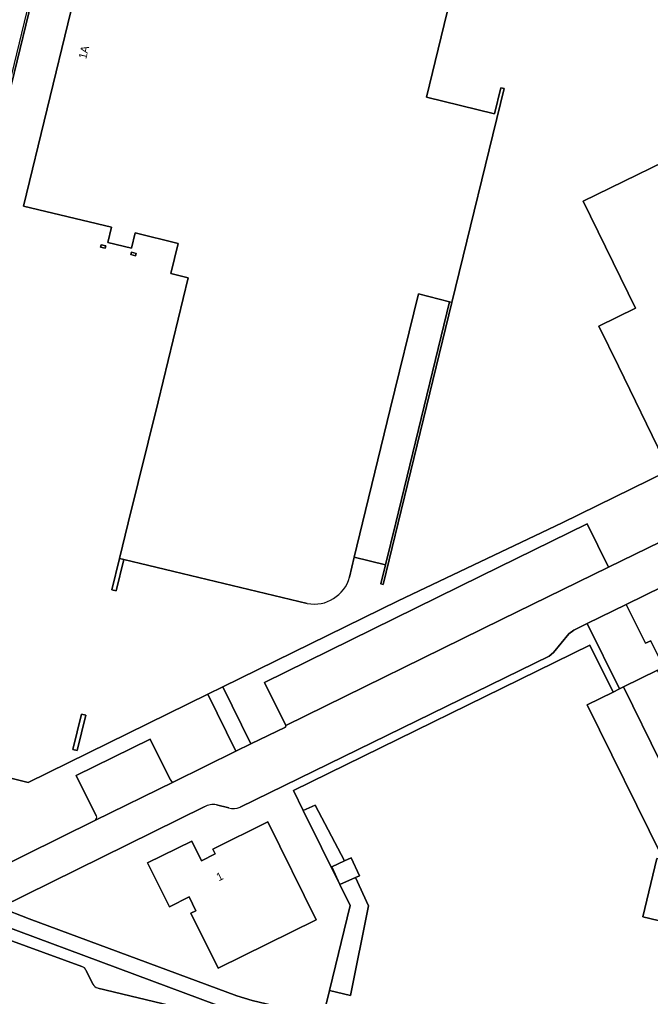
# Model space of a CAD drawing. Extents: x 163043 to 165076, y 382019 to 382874.
# Drawn here: x 163174.8 to 163253.6, y 382690.8 to 382812.9 of the extents above; entities that cross this region are included whole.
import ezdxf

# ---------------------------------------------------------------- set-up
doc = ezdxf.new("R2010")
doc.units = 0
for name, color, linetype in [('IMGEO_Erf', 7, 'Continuous'), ('IMGEO_Fietspad_open', 7, 'Continuous'), ('IMGEO_Groenvoorziening', 7, 'Continuous'), ('IMGEO_Hek', 7, 'Continuous'), ('IMGEO_Loofbos', 7, 'Continuous'), ('IMGEO_Muur', 7, 'Continuous'), ('IMGEO_Pand', 7, 'Continuous'), ('IMGEO_Pand_nummerreeks', 7, 'Continuous'), ('IMGEO_Parkeervlak_open', 7, 'Continuous'), ('IMGEO_Rijbaan_lokaal_gesloten', 7, 'Continuous'), ('IMGEO_Rijbaan_lokaal_open', 7, 'Continuous'), ('IMGEO_Voetpad_open', 7, 'Continuous')]:
    doc.layers.add(name, color=color, linetype=linetype)

msp = doc.modelspace()

# ---------------------------------------------------------------- linework, layer by layer
at = {"layer": 'IMGEO_Erf'}
for points in [[(163360.61, 382802.83), (163320.19, 382810.11), (163314.65, 382811.1), (163314.26, 382811.17), (163314.35, 382812.18), (163260.67, 382823.11), (163260.43, 382821.93), (163260.28, 382821.96), (163252.7, 382823.52), (163242.43, 382825.65), (163242.33, 382825.25), (163240, 382825.68), (163241.32, 382832.3), (163232.1, 382834.21), (163234.48, 382827.11), (163183.14, 382837.73), (163182.27, 382837.91), (163182.21, 382837.62), (163181.79, 382837.7), (163171.55, 382795.71), (163170.41, 382791.08), (163170.29, 382791.11)], [(163229.29, 382818.25), (163225.61, 382803.16), (163234.14, 382801.08), (163234.93, 382804.33), (163235.33, 382804.24), (163228.81, 382777.5), (163222.11, 382750), (163220.23, 382742.28)], [(163210.74, 382739.91), (163187.82, 382745.42), (163186.87, 382741.49), (163186.35, 382741.62), (163187.29, 382745.55), (163188.39, 382750), (163192.11, 382765.11), (163195.86, 382780.59), (163193.71, 382781.12), (163194.64, 382784.88), (163189.27, 382786.19), (163188.81, 382784.29), (163185.83, 382785), (163186.29, 382786.91), (163175.29, 382789.56), (163181.21, 382813.84)], [(163170.08, 382790.67), (163166.83, 382776.84), (163169.38, 382776.24), (163169.07, 382774.97), (163168.15, 382770.94), (163167.89, 382771), (163167.47, 382769.28), (163156.04, 382722.53), (163161.49, 382721.16), (163163.24, 382720.72), (163175.88, 382717.55), (163198.33, 382728.59), (163200.21, 382729.51), (163222.08, 382740.26), (163242.58, 382750), (163320.84, 382788.38)], [(163220.23, 382742.28), (163219.93, 382742.36), (163220.5, 382744.72), (163216.6, 382745.71), (163216.01, 382743.2)]]:
    msp.add_lwpolyline(points, dxfattribs=at)
for points in [[(163260.37, 382797.58), (163257.72, 382803.04), (163272.56, 382810.28), (163275.22, 382804.81), (163285.92, 382810.05), (163288.8, 382804.14), (163299.84, 382781.52), (163300.53, 382780.1), (163259.8, 382760.22), (163255.22, 382757.98), (163249.59, 382769.57), (163247.16, 382774.53), (163251.73, 382776.78), (163245.19, 382790.17)], [(163185.58, 382784.57), (163185.5, 382784.28), (163184.92, 382784.43), (163185, 382784.72)], [(163189.29, 382783.33), (163188.71, 382783.49), (163188.79, 382783.78), (163189.37, 382783.62)], [(163182.01, 382721.54), (163181.48, 382721.67), (163182.56, 382726.09), (163183.08, 382725.96)]]:
    msp.add_lwpolyline(points, close=True, dxfattribs=at)
msp.add_arc((163211.6, 382744.41), 4.58, 259.2784, 344.701, dxfattribs=at)
at = {"layer": 'IMGEO_Fietspad_open'}
msp.add_lwpolyline([(163172.54, 382699.75), (163201.62, 382688.96), (163202.36, 382688.7), (163203.95, 382688.31), (163252.01, 382676.83), (163252.46, 382678.73), (163203.88, 382690.32), (163201.96, 382690.91), (163176, 382700.52), (163172.35, 382701.93), (163168.8, 382700.21), (163171.68, 382699.94)], close=True, dxfattribs=at)
at = {"layer": 'IMGEO_Groenvoorziening'}
for points in [[(163181.79, 382837.7), (163182.21, 382837.62), (163182.27, 382837.91), (163183.69, 382844.16), (163173.42, 382846.23), (163165.78, 382803.62), (163171.55, 382795.71)], [(163253.66, 382735.24), (163252.99, 382734.96), (163250.57, 382739.8), (163245.68, 382737.41), (163249.72, 382729.24), (163250.24, 382729.49), (163254.47, 382731.57), (163266.57, 382707.08), (163265.7, 382703.66), (163271.64, 382702.24), (163272.62, 382706.27), (163267.35, 382707.42)]]:
    msp.add_lwpolyline(points, close=True, dxfattribs=at)
for points in [[(163320.84, 382788.38), (163242.58, 382750), (163222.08, 382740.26), (163200.21, 382729.51), (163203.71, 382722.37), (163208.02, 382724.48), (163208.06, 382724.68), (163205.42, 382730.04), (163232.39, 382743.33), (163245.68, 382749.88), (163248.36, 382744.45), (163259.7, 382750)], [(163271.32, 382750), (163250.57, 382739.8), (163252.99, 382734.96), (163253.66, 382735.24)], [(163194.09, 382717.65), (163201.83, 382721.45), (163198.33, 382728.59), (163175.88, 382717.55), (163163.24, 382720.72), (163159.5, 382704.97), (163166.78, 382704.19), (163184.23, 382712.81)], [(163181.88, 382718.44), (163191.13, 382722.98), (163193.64, 382717.92)], [(163184.4, 382713.38), (163181.88, 382718.44)]]:
    msp.add_lwpolyline(points, dxfattribs=at)
for centre, radius, start, end in [((163194, 382718.02), 0.379, 195.2459, 283.2376), ((163184.01, 382713.19), 0.438, 299.8007, 25.7543)]:
    msp.add_arc(centre, radius, start, end, dxfattribs=at)
at = {"layer": 'IMGEO_Hek'}
for points in [[(163182.27, 382837.91), (163181.98, 382837.97), (163181.57, 382838.06), (163171.31, 382795.84), (163168.94, 382796.43)], [(163359.37, 382797.83), (163352.45, 382797.4), (163349.43, 382797.09), (163343.5, 382795.94), (163337.67, 382794.6), (163334.82, 382793.72), (163329.21, 382791.76), (163326.4, 382790.68), (163320.84, 382788.38), (163242.58, 382750), (163222.08, 382740.26)], [(163222.08, 382740.26), (163175.88, 382717.55), (163161.49, 382721.16)]]:
    msp.add_lwpolyline(points, dxfattribs=at)
at = {"layer": 'IMGEO_Loofbos'}
msp.add_lwpolyline([(163245.69, 382727.26), (163248.93, 382728.85), (163246.01, 382734.71), (163209.01, 382716.54), (163210.24, 382714.06), (163211.73, 382714.73), (163215.4, 382707.75), (163216.23, 382708.13), (163217.25, 382705.9), (163216.76, 382705.68), (163218.39, 382702.14), (163216.15, 382690.95), (163213.5, 382691.55), (163213.05, 382689.7), (163252.81, 382680.18), (163257.5, 382699.61), (163252.63, 382700.77), (163254.38, 382708.07), (163259.27, 382706.86), (163259.68, 382708.74), (163259.48, 382710.67), (163254.98, 382708.45)], close=True, dxfattribs=at)
at = {"layer": 'IMGEO_Muur'}
for points in [[(163220.5, 382744.72), (163219.93, 382742.36), (163220.23, 382742.28), (163222.11, 382750), (163228.81, 382777.5), (163228.51, 382777.59), (163221.79, 382750)], [(163186.87, 382741.49), (163187.82, 382745.42), (163187.29, 382745.55), (163186.35, 382741.62)], [(163182.56, 382726.09), (163181.48, 382721.67), (163182.01, 382721.54), (163183.08, 382725.96)]]:
    msp.add_lwpolyline(points, close=True, dxfattribs=at)
at = {"layer": 'IMGEO_Pand'}
for points in [[(163216.01, 382743.2), (163216.6, 382745.71), (163217.65, 382750), (163221.11, 382764.2), (163224.63, 382778.58), (163228.51, 382777.59), (163228.81, 382777.5), (163235.33, 382804.24), (163234.93, 382804.33), (163234.14, 382801.08), (163225.61, 382803.16), (163229.29, 382818.25)], [(163181.21, 382813.84), (163175.29, 382789.56), (163186.29, 382786.91), (163185.83, 382785), (163188.81, 382784.29), (163189.27, 382786.19), (163194.64, 382784.88), (163193.71, 382781.12), (163195.86, 382780.59), (163192.11, 382765.11), (163188.39, 382750), (163187.29, 382745.55), (163187.82, 382745.42), (163210.74, 382739.91)]]:
    msp.add_lwpolyline(points, dxfattribs=at)
for points in [[(163249.59, 382769.57), (163255.22, 382757.98), (163259.8, 382760.22), (163300.53, 382780.1), (163299.84, 382781.52), (163288.8, 382804.14), (163285.92, 382810.05), (163275.22, 382804.81), (163272.56, 382810.28), (163257.72, 382803.04), (163260.37, 382797.58), (163245.19, 382790.17), (163251.73, 382776.78), (163247.16, 382774.53)], [(163185.58, 382784.57), (163185, 382784.72), (163184.92, 382784.43), (163185.5, 382784.28)], [(163188.71, 382783.49), (163189.29, 382783.33), (163189.37, 382783.62), (163188.79, 382783.78)], [(163199.63, 382694.34), (163211.85, 382700.39), (163205.82, 382712.62), (163198.95, 382709.22), (163199.24, 382708.63), (163197.53, 382707.78), (163196.32, 382710.24), (163190.8, 382707.52), (163193.55, 382702.02), (163196.01, 382703.25), (163196.83, 382701.53), (163196.2, 382701.21)], [(163215.4, 382707.75), (163213.8, 382707.02), (163214.82, 382704.79), (163216.76, 382705.68), (163217.25, 382705.9), (163216.23, 382708.13)]]:
    msp.add_lwpolyline(points, close=True, dxfattribs=at)
msp.add_arc((163211.6, 382744.41), 4.58, 259.2784, 344.701, dxfattribs=at)
at = {"layer": 'IMGEO_Parkeervlak_open'}
for points in [[(163235.01, 382737.92), (163248.36, 382744.45), (163245.68, 382749.88), (163232.39, 382743.33), (163205.42, 382730.04), (163208.06, 382724.68)], [(163250.24, 382729.49), (163249.72, 382729.24), (163248.93, 382728.85), (163245.69, 382727.26), (163254.98, 382708.45), (163259.48, 382710.67)], [(163211.73, 382714.73), (163210.24, 382714.06), (163214.82, 382704.79), (163213.8, 382707.02), (163215.4, 382707.75)], [(163259.27, 382706.86), (163254.38, 382708.07), (163252.63, 382700.77), (163257.5, 382699.61)], [(163218.39, 382702.14), (163216.76, 382705.68), (163214.82, 382704.79), (163216.09, 382702.18), (163213.5, 382691.55), (163216.15, 382690.95)]]:
    msp.add_lwpolyline(points, close=True, dxfattribs=at)
for points in [[(163193.64, 382717.92), (163191.13, 382722.98), (163181.88, 382718.44), (163184.4, 382713.38)], [(163184.23, 382712.81), (163194.09, 382717.65)]]:
    msp.add_lwpolyline(points, dxfattribs=at)
for centre, radius, start, end in [((163194, 382718.02), 0.379, 195.2459, 283.2376), ((163184.01, 382713.19), 0.438, 299.8007, 25.7543)]:
    msp.add_arc(centre, radius, start, end, dxfattribs=at)
at = {"layer": 'IMGEO_Rijbaan_lokaal_gesloten'}
for points in [[(163323, 382780.97), (163259.7, 382750), (163248.36, 382744.45), (163235.01, 382737.92), (163208.06, 382724.68), (163208.02, 382724.48), (163203.71, 382722.37), (163201.83, 382721.45), (163194.09, 382717.65), (163184.23, 382712.81), (163166.78, 382704.19), (163164.05, 382702.84), (163162.09, 382701.87)], [(163202.36, 382714.48), (163240.95, 382733.35), (163241.47, 382733.79), (163243.4, 382736.12), (163244.02, 382736.59), (163245.68, 382737.41), (163250.57, 382739.8), (163271.32, 382750), (163327.66, 382777.68)], [(163157.18, 382701.57), (163165.67, 382698.64), (163168.07, 382699.85), (163168.61, 382700.12), (163168.8, 382700.21), (163172.35, 382701.93), (163197.88, 382714.53)], [(163199.4, 382714.75), (163200.93, 382714.39)], [(163182.59, 382694.58), (163168.65, 382699.64)], [(163183.98, 382692.36), (163183.15, 382694.06)], [(163251.29, 382675.9), (163203.7, 382687.3), (163184.58, 382691.88)]]:
    msp.add_lwpolyline(points, dxfattribs=at)
msp.add_lwpolyline([(163221.79, 382750), (163228.51, 382777.59), (163224.63, 382778.58), (163221.11, 382764.2), (163217.65, 382750), (163216.6, 382745.71), (163220.5, 382744.72)], close=True, dxfattribs=at)
for centre, radius, start, end in [((163198.95, 382712.61), 2.19, 77.9738, 119.014), ((163201.52, 382716.2), 1.91, 251.7554, 295.8303), ((163182.31, 382693.72), 0.902, 22.0668, 72.1754), ((163184.79, 382692.76), 0.899, 206.0966, 256.5137)]:
    msp.add_arc(centre, radius, start, end, dxfattribs=at)
at = {"layer": 'IMGEO_Rijbaan_lokaal_open'}
msp.add_lwpolyline([(163266.57, 382707.08), (163254.47, 382731.57), (163250.24, 382729.49), (163259.48, 382710.67), (163259.68, 382708.74), (163259.27, 382706.86), (163257.5, 382699.61), (163252.81, 382680.18), (163256.9, 382679.25), (163257.28, 382680.85), (163260.84, 382695.84), (163263.63, 382697.4), (163264.44, 382697.21), (163265.45, 382696.98), (163269.34, 382696.11), (163269.61, 382697.11), (163271.83, 382699.41), (163273.02, 382699.15), (163273.47, 382701.08), (163272.36, 382701.35), (163272.52, 382702.03), (163271.64, 382702.24), (163265.7, 382703.66)], close=True, dxfattribs=at)
at = {"layer": 'IMGEO_Voetpad_open'}
for points in [[(163216.09, 382702.18), (163214.82, 382704.79), (163210.24, 382714.06), (163209.01, 382716.54), (163246.01, 382734.71), (163248.93, 382728.85), (163249.72, 382729.24), (163245.68, 382737.41), (163244.02, 382736.59), (163243.4, 382736.12), (163241.47, 382733.79), (163240.95, 382733.35), (163202.36, 382714.48)], [(163197.88, 382714.53), (163172.35, 382701.93), (163176, 382700.52), (163201.96, 382690.91), (163203.88, 382690.32), (163252.46, 382678.73), (163252.81, 382680.18), (163213.05, 382689.7), (163213.5, 382691.55), (163216.09, 382702.18)], [(163200.93, 382714.39), (163199.4, 382714.75)], [(163168.65, 382699.64), (163182.59, 382694.58)], [(163251.88, 382676.26), (163252.01, 382676.83), (163203.95, 382688.31), (163202.36, 382688.7), (163201.62, 382688.96), (163172.54, 382699.75)], [(163183.15, 382694.06), (163183.98, 382692.36)], [(163184.58, 382691.88), (163203.7, 382687.3), (163251.29, 382675.9)]]:
    msp.add_lwpolyline(points, dxfattribs=at)
for points in [[(163200.21, 382729.51), (163198.33, 382728.59), (163201.83, 382721.45), (163203.71, 382722.37)], [(163196.2, 382701.21), (163196.83, 382701.53), (163196.01, 382703.25), (163193.55, 382702.02), (163190.8, 382707.52), (163196.32, 382710.24), (163197.53, 382707.78), (163199.24, 382708.63), (163198.95, 382709.22), (163205.82, 382712.62), (163211.85, 382700.39), (163199.63, 382694.34)]]:
    msp.add_lwpolyline(points, close=True, dxfattribs=at)
for centre, radius, start, end in [((163198.95, 382712.61), 2.19, 77.9738, 119.014), ((163201.52, 382716.2), 1.91, 251.7554, 295.8303), ((163182.31, 382693.72), 0.902, 22.0668, 72.1754), ((163184.79, 382692.76), 0.899, 206.0966, 256.5137)]:
    msp.add_arc(centre, radius, start, end, dxfattribs=at)

# ---------------------------------------------------------------- texts
at = {"layer": 'IMGEO_Pand_nummerreeks'}
for s, rotation, p in [('1A', 76.2884, (163183.13, 382807.85)), ('1', 26.4309, (163199.7, 382705.2))]:
    msp.add_text(s, height=1, rotation=rotation, dxfattribs=at).set_placement(p)

doc.saveas('drawing.dxf')
